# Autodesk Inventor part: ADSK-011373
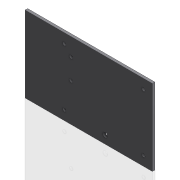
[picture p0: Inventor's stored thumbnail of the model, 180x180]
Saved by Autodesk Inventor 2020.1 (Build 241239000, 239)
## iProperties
Created: 2000-02
Part Number: ADSK-011373
Material: Pearson HRS
Document SubType Name: Modeling
Designer: glanglot
Density: 7.83 g/cm^3
Appearance: Métal - Acier
Mass: 1500.98 g
Surface Area: 815.016 cm^2
Volume: 191.696 cm^3
Control State: 0
Checked Out: False
Master: False
Shininess: 0.0
Length Units: 11269
Angle Units: 11279
Time Units: 11290
Mass Units: 11283
Length Display Precision: 3
Angle Display Precision: 2
Compacted: True
Cutlength: 23.25
Material Desc: Material Description goes here
Material_Number: Pearson
Dimensions: 254x152x5 mm
Mass: 1,501 kg
DocNumber: ADSK-011373.ipt
Folder: 01 - Themengebiete\Simplification\01 - Packaging machine\
VDS_Category: 3D Komponenten
Density: 0.0
Volumn: 0.0
Area: 0.0
PropertySet Name: Model Information
Author: glanglot
Revision Number: -
Title: plate
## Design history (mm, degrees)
node "Solide1"
  node "Extrusion1" dims "d3" = 5, "d4" = 0
  node "Hole1" dims "d13" = 6.6, "d14" = 9.525, "d15" = 6.35, "d16" = 60 deg, "d17" = 19.05, "d18" = 118 deg, "d34" = 6
  node "Hole2" dims "d25" = 9, "d26" = 9.525, "d27" = 6.35, "d28" = 60 deg, "d29" = 19.05, "d30" = 118 deg, "d35" = 6
sketch "Sketch1"
  geometry: L1 (0, 0)-(254, 0); L2 (254, 0)-(254, 152); L3 (254, 152)-(0, 152); L4 (0, 152)-(0, 0)
  constraints: 8 end point, 2 parallel, 1 horizontal, 1 perpendicular
  dimensions: "d1" = 152 distance between parallel lines of L1 L3; "d2" = 254 distance between parallel lines of L2 L4
sketch "Sketch2"
  geometry: L1 (254, 152)-(254, 0) reference; L2 (0, 152)-(254, 152) reference; L3 (254, 0)-(0, 0) reference; L4 (78.5, 133)-(236.5, 133); L5 (236.5, 133)-(236.5, 19); L6 (236.5, 19)-(78.5, 19); L7 (78.5, 19)-(78.5, 133); L8 (92, 117)-(92, 76); 5 further points
  constraints: 10 end point, 2 coincident, 2 midpoint, 2 parallel, 1 horizontal, 1 horizontal alignment, 1 perpendicular, 1 vertical, 1 vertical alignment
  dimensions: "d19" = 94 distance from line of L1 point (160, 16); "d20" = 16 distance from line of point (160, 16) L3; "d22" = 162 distance from line of L1 L8.end; "d23" = 35 distance from line of L8.start L2; "d24" = 76 distance from line of L8.end L2; "d31" = 17.5 distance between parallel lines of L1 L5; "d32" = 158 distance of L5.end L6.end; "d33" = 114 distance of L6.end L4.start
node "Corps solides"
node "Corps surfaciques"
